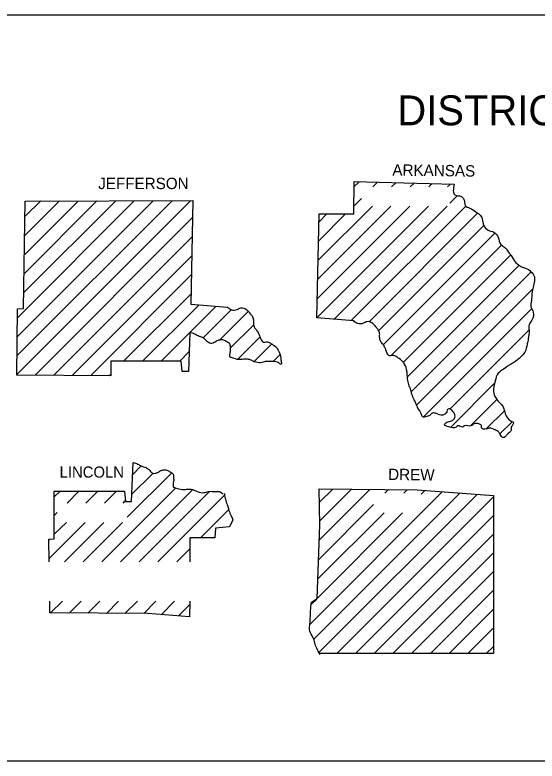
# Model space of a CAD drawing. Extents: x 21307 to 29830, y 1322443 to 1332359.
# Drawn here: x 27755.3 to 27952.8, y 1327341.4 to 1327623.3 of the extents above; entities that cross this region are included whole.
import ezdxf

# ---------------------------------------------------------------- set-up
doc = ezdxf.new("R2010")
doc.units = 0
doc.layers.add('R_Draft', color=7, linetype='Continuous')

msp = doc.modelspace()

# ---------------------------------------------------------------- linework, layer by layer
at = {"layer": 'R_Draft'}
msp.add_lwpolyline([(28149.74, 1327341.43), (27743.64, 1327341.43), (27743.64, 1327623.33), (28149.74, 1327623.33)], close=True, dxfattribs=at)
for points in [[(27870.34, 1327548.13), (27883.44, 1327548.13), (27883.64, 1327560.43), (27921.44, 1327559.43)], [(27883.54, 1327558.33), (27885.54, 1327560.33)], [(27890.64, 1327558.33), (27892.44, 1327560.13)], [(27897.74, 1327558.33), (27899.34, 1327559.93)], [(27904.74, 1327558.33), (27906.24, 1327559.83)], [(27911.84, 1327558.33), (27913.14, 1327559.63)], [(27918.94, 1327558.33), (27920.04, 1327559.43)], [(27919.84, 1327552.23), (27922.54, 1327554.93)], [(27756.04, 1327487.23), (27756.34, 1327512.33), (27758.64, 1327512.43), (27759.24, 1327553.03), (27822.64, 1327553.23)], [(27756.04, 1327487.43), (27821.74, 1327553.13)], [(27756.14, 1327494.63), (27814.74, 1327553.13)], [(27756.24, 1327501.73), (27807.64, 1327553.13)], [(27756.34, 1327508.93), (27800.44, 1327553.13)], [(27758.84, 1327518.53), (27793.44, 1327553.13)], [(27758.94, 1327525.63), (27786.34, 1327553.13)], [(27759.04, 1327532.83), (27779.24, 1327553.03)], [(27759.14, 1327540.03), (27772.24, 1327553.13)], [(27759.14, 1327547.13), (27765.14, 1327553.13)], [(27822.64, 1327553.23), (27821.84, 1327514.03), (27835.74, 1327512.93)], [(27883.44, 1327551.13), (27886.34, 1327554.03)], [(27869.64, 1327509.03), (27911.74, 1327551.13)], [(27869.74, 1327516.23), (27904.64, 1327551.13)], [(27869.94, 1327523.53), (27897.54, 1327551.13)], [(27870.04, 1327530.73), (27890.54, 1327551.13)], [(27876.04, 1327508.33), (27918.84, 1327551.13)], [(27882.54, 1327507.83), (27925.84, 1327551.13)], [(27762.94, 1327487.23), (27822.54, 1327546.83)], [(27883.44, 1327507.73), (27869.54, 1327508.83), (27870.34, 1327548.13)], [(27870.24, 1327537.93), (27880.34, 1327548.13)], [(27870.34, 1327545.13), (27873.34, 1327548.13)], [(27889.24, 1327507.43), (27930.14, 1327548.33)], [(27892.94, 1327504.13), (27932.64, 1327543.73)], [(27894.74, 1327498.83), (27936.84, 1327540.83)], [(27769.94, 1327487.13), (27822.34, 1327539.53)], [(27897.64, 1327494.63), (27939.34, 1327536.33)], [(27777.04, 1327487.13), (27822.24, 1327532.33)], [(27902.24, 1327492.13), (27942.74, 1327532.63)], [(27903.74, 1327486.63), (27945.94, 1327528.83)], [(27905.24, 1327481.03), (27950.54, 1327526.33)], [(27784.04, 1327487.13), (27822.04, 1327525.13)], [(27796.44, 1327492.53), (27821.94, 1327517.93)], [(27907.24, 1327475.93), (27950.94, 1327519.63)], [(27803.54, 1327492.53), (27824.84, 1327513.73)], [(27810.64, 1327492.53), (27831.34, 1327513.23)], [(27826.54, 1327501.33), (27837.14, 1327511.93)], [(27832.74, 1327500.43), (27843.54, 1327511.33)], [(27909.84, 1327471.43), (27950.54, 1327512.13)], [(27836.74, 1327497.43), (27845.64, 1327506.23)], [(27919.94, 1327474.53), (27949.74, 1327504.33)], [(27821.54, 1327503.33), (27820.94, 1327488.63), (27818.64, 1327488.63), (27818.24, 1327492.53), (27791.64, 1327492.53), (27791.64, 1327487.03)], [(27839.54, 1327493.13), (27847.94, 1327501.53)], [(27845.74, 1327492.23), (27852.44, 1327499.03)], [(27817.64, 1327492.53), (27821.24, 1327496.13)], [(27852.94, 1327492.43), (27855.54, 1327494.93)], [(27791.44, 1327487.03), (27756.04, 1327487.23)], [(27791.04, 1327487.13), (27791.64, 1327487.63)], [(27920.24, 1327467.73), (27936.84, 1327484.33)], [(27927.64, 1327468.03), (27937.64, 1327478.13)], [(27918.14, 1327472.73), (27918.44, 1327473.03), (27918.74, 1327473.33), (27918.74, 1327473.33)], [(27933.54, 1327466.93), (27940.54, 1327473.93)], [(27938.74, 1327465.03), (27943.34, 1327469.63)], [(27768.34, 1327416.73), (27768.14, 1327425.33), (27770.24, 1327425.43), (27770.14, 1327443.43), (27796.74, 1327443.43), (27797.14, 1327439.53), (27799.44, 1327439.53), (27800.04, 1327454.23)], [(27797.84, 1327433.53), (27814.64, 1327450.33)], [(27799.84, 1327449.63), (27803.14, 1327452.93)], [(27799.44, 1327442.13), (27807.44, 1327450.13)], [(27788.24, 1327416.73), (27816.14, 1327444.63)], [(27770.24, 1327441.23), (27772.44, 1327443.43)], [(27775.04, 1327438.93), (27779.54, 1327443.43)], [(27782.14, 1327438.93), (27786.54, 1327443.33)], [(27789.24, 1327438.93), (27793.64, 1327443.33)], [(27795.24, 1327416.73), (27822.44, 1327443.93)], [(27802.34, 1327416.73), (27828.94, 1327443.33)], [(27809.44, 1327416.73), (27834.54, 1327441.93)], [(27866.94, 1327393.13), (27916.94, 1327443.13)], [(27868.34, 1327387.53), (27923.54, 1327442.63)], [(27870.34, 1327444.23), (27907.44, 1327443.93), (27936.24, 1327441.73)], [(27870.64, 1327430.63), (27870.44, 1327444.23)], [(27870.44, 1327382.53), (27930.14, 1327442.13)], [(27870.54, 1327439.23), (27875.54, 1327444.13)], [(27870.54, 1327425.03), (27889.54, 1327444.03)], [(27870.64, 1327432.23), (27882.54, 1327444.03)], [(27895.24, 1327442.63), (27896.64, 1327444.03)], [(27902.34, 1327442.63), (27903.64, 1327443.93)], [(27908.94, 1327442.23), (27910.34, 1327443.63)], [(27936.24, 1327441.73), (27936.24, 1327382.03)], [(27796.24, 1327438.93), (27797.04, 1327439.73)], [(27877.04, 1327382.03), (27936.14, 1327441.13)], [(27825.54, 1327425.83), (27836.14, 1327436.33)], [(27870.24, 1327417.63), (27890.94, 1327438.33)], [(27770.24, 1327434.23), (27771.34, 1327435.33)], [(27869.74, 1327403.03), (27901.94, 1327435.23)], [(27869.94, 1327410.23), (27894.94, 1327435.23)], [(27884.14, 1327382.03), (27936.14, 1327434.13)], [(27768.34, 1327418.03), (27781.94, 1327431.63)], [(27770.24, 1327427.13), (27774.84, 1327431.63)], [(27774.04, 1327416.73), (27788.94, 1327431.63)], [(27781.14, 1327416.73), (27796.04, 1327431.63)], [(27837.74, 1327432.63), (27836.54, 1327429.93), (27831.24, 1327429.43), (27830.94, 1327425.83), (27821.44, 1327425.83), (27821.44, 1327416.73)], [(27867.44, 1327401.43), (27869.64, 1327402.83), (27870.64, 1327430.63)], [(27768.24, 1327425.03), (27768.54, 1327425.33)], [(27891.24, 1327382.03), (27936.14, 1327427.03)], [(27816.54, 1327416.73), (27821.44, 1327421.63)], [(27898.24, 1327382.03), (27936.14, 1327419.93)], [(27905.34, 1327382.03), (27936.14, 1327412.93)], [(27912.44, 1327382.03), (27936.14, 1327405.83)], [(27867.34, 1327400.63), (27869.34, 1327402.53)], [(27768.54, 1327397.43), (27768.54, 1327401.83)], [(27768.84, 1327397.43), (27773.34, 1327401.83)], [(27775.94, 1327397.43), (27780.34, 1327401.83)], [(27782.94, 1327397.33), (27787.44, 1327401.83)], [(27789.94, 1327397.23), (27794.54, 1327401.83)], [(27796.94, 1327397.23), (27801.64, 1327401.83)], [(27804.04, 1327397.23), (27808.64, 1327401.83)], [(27810.64, 1327396.73), (27815.74, 1327401.83)], [(27817.24, 1327396.33), (27821.44, 1327400.53)], [(27821.44, 1327401.83), (27821.34, 1327395.93)], [(27821.34, 1327395.93), (27805.54, 1327397.13), (27768.44, 1327397.43)], [(27919.54, 1327382.03), (27936.14, 1327398.73)], [(27926.54, 1327382.03), (27936.14, 1327391.63)], [(27933.54, 1327382.03), (27936.14, 1327384.63)], [(27936.24, 1327382.03), (27870.74, 1327382.03)]]:
    msp.add_lwpolyline(points, dxfattribs=at)
for points in [[(27921.44, 1327559.43), (27921.74, 1327555.33), (27924.14, 1327554.73), (27925.14, 1327553.63), (27925.64, 1327551.33), (27927.34, 1327550.33), (27929.64, 1327548.93), (27931.04, 1327547.93), (27932.04, 1327546.33), (27932.64, 1327543.73), (27934.24, 1327542.03), (27936.44, 1327541.23), (27938.04, 1327539.33), (27939.04, 1327536.63), (27940.64, 1327535.43), (27942.24, 1327533.33), (27943.04, 1327532.43), (27944.44, 1327530.03), (27945.84, 1327528.83), (27946.84, 1327528.13), (27948.44, 1327527.63), (27950.44, 1327526.33), (27951.74, 1327524.33), (27951.74, 1327522.83), (27951.24, 1327520.53), (27950.84, 1327518.13), (27950.64, 1327515.43), (27950.44, 1327513.03), (27951.34, 1327511.03), (27950.84, 1327508.03), (27949.84, 1327506.43), (27949.74, 1327504.23), (27949.44, 1327500.93), (27949.04, 1327499.03), (27948.14, 1327495.93), (27946.54, 1327494.03)], [(27835.74, 1327512.93), (27837.24, 1327511.93), (27839.34, 1327512.03), (27840.74, 1327512.63), (27841.84, 1327512.53), (27843.34, 1327511.63), (27844.34, 1327510.43), (27845.04, 1327509.53), (27845.54, 1327508.13), (27845.54, 1327506.83), (27846.04, 1327505.03), (27846.64, 1327504.33), (27847.44, 1327503.03), (27847.94, 1327501.83), (27848.24, 1327501.03), (27849.34, 1327499.73), (27850.34, 1327499.83), (27851.24, 1327499.73), (27852.44, 1327499.03), (27854.24, 1327497.63), (27854.54, 1327497.23), (27855.74, 1327494.63), (27855.94, 1327493.03), (27856.14, 1327491.43)], [(27943.84, 1327469.13), (27943.34, 1327468.13), (27942.94, 1327467.43), (27942.94, 1327466.43), (27941.44, 1327464.83), (27940.74, 1327463.93), (27939.84, 1327463.63), (27938.84, 1327464.83), (27938.04, 1327465.93), (27936.54, 1327466.73), (27934.84, 1327467.23), (27933.54, 1327466.93), (27931.74, 1327467.33), (27931.74, 1327468.23), (27931.04, 1327468.73), (27928.84, 1327468.83), (27927.74, 1327468.03), (27925.34, 1327468.13), (27924.64, 1327467.63), (27922.84, 1327468.13), (27922.14, 1327467.53), (27919.44, 1327467.73), (27917.74, 1327468.53), (27918.24, 1327469.23), (27920.04, 1327469.83), (27921.34, 1327470.63), (27921.74, 1327471.23), (27921.74, 1327472.23), (27920.64, 1327473.83), (27919.64, 1327474.53), (27918.74, 1327474.03), (27918.64, 1327473.13), (27918.14, 1327472.73), (27917.14, 1327472.13), (27915.54, 1327472.43), (27914.34, 1327472.83), (27913.24, 1327472.93), (27912.34, 1327472.13), (27911.14, 1327471.63), (27909.44, 1327471.53), (27908.94, 1327472.73), (27907.74, 1327474.73), (27906.94, 1327476.53), (27906.34, 1327477.93), (27905.44, 1327480.03), (27905.04, 1327481.53), (27904.24, 1327483.73), (27903.84, 1327485.73), (27903.64, 1327487.83), (27903.44, 1327489.43), (27902.24, 1327492.03), (27901.94, 1327492.43), (27900.14, 1327493.83), (27898.94, 1327494.53), (27898.04, 1327494.63), (27897.04, 1327494.53), (27895.94, 1327495.83), (27895.64, 1327496.63), (27895.14, 1327497.83), (27894.34, 1327499.13), (27893.74, 1327499.83), (27893.24, 1327501.63), (27893.24, 1327502.93), (27892.74, 1327504.33), (27892.04, 1327505.23), (27891.04, 1327506.43), (27889.54, 1327507.33), (27888.44, 1327507.43), (27887.04, 1327506.83), (27884.94, 1327506.73), (27883.44, 1327507.73)], [(27856.04, 1327491.23), (27854.04, 1327492.33), (27853.04, 1327492.43), (27851.44, 1327492.43), (27850.44, 1327492.43), (27848.74, 1327492.03), (27847.74, 1327491.93), (27846.54, 1327492.13), (27845.74, 1327492.33), (27844.64, 1327492.93), (27843.34, 1327493.23), (27841.74, 1327493.23), (27840.04, 1327493.13), (27837.54, 1327493.73), (27836.84, 1327494.03), (27836.84, 1327496.13), (27836.84, 1327497.63), (27836.64, 1327498.93), (27835.44, 1327499.83), (27834.34, 1327500.43), (27833.34, 1327500.53), (27832.04, 1327500.33), (27830.74, 1327499.53), (27828.94, 1327499.33), (27827.44, 1327500.63), (27826.34, 1327501.43), (27824.64, 1327502.03), (27823.34, 1327502.73), (27821.54, 1327503.33)], [(27946.54, 1327494.03), (27944.04, 1327492.03), (27942.24, 1327491.03), (27940.34, 1327489.63), (27938.04, 1327487.93), (27936.94, 1327485.03), (27936.34, 1327481.03), (27937.14, 1327478.63), (27938.94, 1327476.53), (27940.14, 1327474.83), (27941.04, 1327471.83), (27943.24, 1327469.73), (27943.94, 1327469.43)], [(27800.04, 1327454.23), (27801.84, 1327453.63), (27803.14, 1327452.93), (27804.84, 1327452.33), (27805.94, 1327451.53), (27807.44, 1327450.23), (27809.24, 1327450.43), (27810.54, 1327451.23), (27811.84, 1327451.43), (27812.84, 1327451.33), (27813.94, 1327450.73), (27815.14, 1327449.83), (27815.34, 1327448.53), (27815.34, 1327447.03), (27815.34, 1327444.93), (27816.04, 1327444.63), (27818.54, 1327444.03), (27820.24, 1327444.13), (27821.84, 1327444.13), (27823.14, 1327443.83), (27824.24, 1327443.23), (27825.04, 1327443.03), (27826.24, 1327442.83), (27827.24, 1327442.93), (27828.94, 1327443.33), (27829.94, 1327443.33), (27831.54, 1327443.33), (27832.54, 1327443.23), (27834.04, 1327442.43)], [(27834.54, 1327442.53), (27834.64, 1327441.83), (27835.04, 1327439.83), (27835.84, 1327437.63), (27836.24, 1327436.13), (27837.14, 1327434.03), (27837.74, 1327432.63)], [(27870.74, 1327381.73), (27869.44, 1327384.13), (27868.74, 1327386.03), (27868.04, 1327388.23), (27866.84, 1327390.53), (27866.84, 1327392.63), (27867.04, 1327395.43), (27867.14, 1327398.33), (27867.44, 1327401.43)]]:
    msp.add_spline(points, degree=3, dxfattribs=at)

# ---------------------------------------------------------------- texts
for s, height, p in [('DISTRICT 2', 11.3, (27899.94, 1327581.63)), ('JEFFERSON', 4.3, (27786.84, 1327557.53)), ('LINCOLN', 4.2, (27772.24, 1327448.53))]:
    msp.add_text(s, height=height, dxfattribs=at).set_placement(p)
for s, rotation, p in [('ARKANSAS', 359.2678, (27898.04, 1327562.63)), ('DREW', 359.2258, (27896.44, 1327447.63))]:
    msp.add_text(s, height=4.3, rotation=rotation, dxfattribs=at).set_placement(p)

doc.saveas('drawing.dxf')
